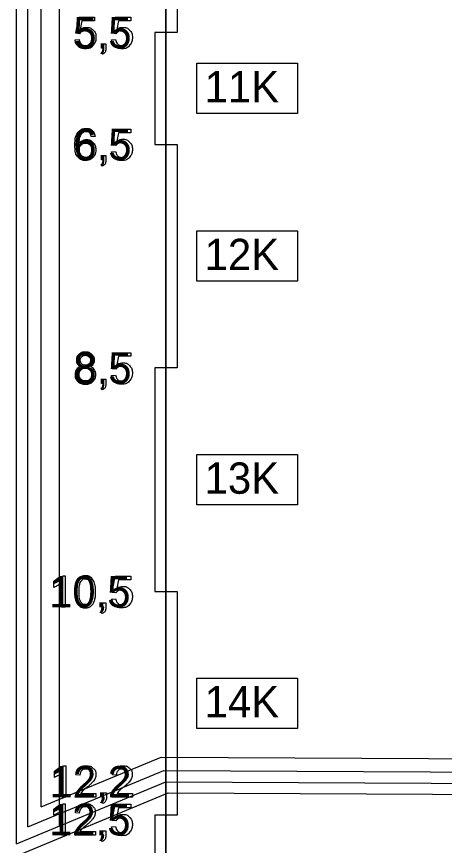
# Model space of a CAD drawing. Extents: x 532503 to 539665, y 6557663 to 6561526.
# Drawn here: x 538143.1 to 538219.7, y 6559684.2 to 6559832.5 of the extents above; entities that cross this region are included whole.
import ezdxf

# ---------------------------------------------------------------- set-up
doc = ezdxf.new("R2010")
doc.units = 0
for name, color, linetype in [('GEOLPUNKT', 7, 'Continuous'), ('illumineerimisjooned', 7, 'Continuous'), ('PIIR', 7, 'Continuous'), ('Plokid', 7, 'Continuous'), ('Proovid', 7, 'Continuous'), ('RELJEEF', 7, 'Continuous')]:
    doc.layers.add(name, color=color, linetype=linetype)

msp = doc.modelspace()

# ---------------------------------------------------------------- linework, layer by layer
at = {"layer": 'GEOLPUNKT'}
msp.add_line((538169.83, 6559939.6), (538169.83, 6559639.6), dxfattribs=at)
at = {"layer": 'illumineerimisjooned'}
msp.add_line((538145.11, 6559687.5), (538145.11, 6559941.71), dxfattribs=at)
msp.add_lwpolyline([(538145.11, 6559687.5), (538169.44, 6559697.61), (538288.54, 6559697), (538442.63, 6559688.61)], dxfattribs=at)
at = {"layer": 'PIIR'}
msp.add_line((538143.11, 6559684.5), (538143.11, 6559941.71), dxfattribs=at)
msp.add_lwpolyline([(538143.11, 6559684.5), (538169.83, 6559695.6), (538288.48, 6559695), (538467.68, 6559685.24), (538608.55, 6559672.2), (538715.29, 6559665.8)], dxfattribs=at)
at = {"layer": 'Plokid'}
msp.add_line((538147.51, 6559691.1), (538147.51, 6559935.16), dxfattribs=at)
for points in [[(538147.51, 6559691.1), (538168.96, 6559700.01), (538288.61, 6559699.4), (538440.23, 6559691.14)], [(538143.88, 6559682.66), (538170.22, 6559693.6), (538288.42, 6559693.01), (538467.54, 6559683.25), (538608.39, 6559670.21), (538713.29, 6559663.92)]]:
    msp.add_lwpolyline(points, dxfattribs=at)
at = {"layer": 'Proovid'}
for points in [[(538169.83, 6559869.6), (538171.83, 6559869.6), (538171.83, 6559829.6), (538169.83, 6559829.6)], [(538169.83, 6559829.6), (538167.83, 6559829.6), (538167.83, 6559809.6), (538169.83, 6559809.6)], [(538175.36, 6559824.1), (538193.36, 6559824.1), (538193.36, 6559815.1), (538175.36, 6559815.1)], [(538169.83, 6559809.6), (538171.83, 6559809.6), (538171.83, 6559769.6), (538169.83, 6559769.6)], [(538175.36, 6559794.1), (538193.36, 6559794.1), (538193.36, 6559785.1), (538175.36, 6559785.1)], [(538169.83, 6559769.6), (538167.83, 6559769.6), (538167.83, 6559729.6), (538169.83, 6559729.6)], [(538175.36, 6559754.1), (538193.36, 6559754.1), (538193.36, 6559745.1), (538175.36, 6559745.1)], [(538169.83, 6559729.6), (538171.83, 6559729.6), (538171.83, 6559689.6), (538169.83, 6559689.6)], [(538175.36, 6559714.1), (538193.36, 6559714.1), (538193.36, 6559705.1), (538175.36, 6559705.1)], [(538169.83, 6559689.6), (538167.83, 6559689.6), (538167.83, 6559639.6), (538169.83, 6559639.6)]]:
    msp.add_lwpolyline(points, close=True, dxfattribs=at)
for points in [[(538154.36, 6559829.37), (538153.72, 6559829.46), (538154.26, 6559832.33), (538157.04, 6559832.33), (538157.04, 6559831.68), (538154.81, 6559831.68), (538154.51, 6559830.17)], [(538160.88, 6559829.37), (538160.24, 6559829.46), (538160.78, 6559832.33), (538163.57, 6559832.33), (538163.57, 6559831.68), (538161.33, 6559831.68), (538161.03, 6559830.17)], [(538153.59, 6559828.27), (538154.32, 6559828.33)], [(538158.32, 6559826.8), (538158.32, 6559827.59), (538159.1, 6559827.59), (538159.1, 6559826.8)], [(538160.12, 6559828.27), (538160.84, 6559828.33)], [(538158.46, 6559825.7), (538158.27, 6559825.99)], [(538158.7, 6559826.8), (538158.32, 6559826.8)], [(538160.88, 6559809.37), (538160.24, 6559809.46), (538160.78, 6559812.33), (538163.57, 6559812.33), (538163.57, 6559811.68), (538161.33, 6559811.68), (538161.03, 6559810.17)], [(538157.17, 6559811.03), (538156.48, 6559810.98)], [(538160.12, 6559808.27), (538160.84, 6559808.33)], [(538158.32, 6559806.8), (538158.32, 6559807.59), (538159.1, 6559807.59), (538159.1, 6559806.8)], [(538158.7, 6559806.8), (538158.32, 6559806.8)], [(538158.46, 6559805.7), (538158.27, 6559805.99)], [(538160.88, 6559769.37), (538160.24, 6559769.46), (538160.78, 6559772.33), (538163.57, 6559772.33), (538163.57, 6559771.68), (538161.33, 6559771.68), (538161.03, 6559770.17)], [(538160.12, 6559768.27), (538160.84, 6559768.33)], [(538158.32, 6559766.8), (538158.32, 6559767.59), (538159.1, 6559767.59), (538159.1, 6559766.8)], [(538158.7, 6559766.8), (538158.32, 6559766.8)], [(538158.46, 6559765.7), (538158.27, 6559765.99)], [(538151.39, 6559732.43), (538151.83, 6559732.43), (538151.83, 6559726.8)], [(538160.88, 6559729.37), (538160.24, 6559729.46), (538160.78, 6559732.33), (538163.57, 6559732.33), (538163.57, 6559731.68), (538161.33, 6559731.68), (538161.03, 6559730.17)], [(538149.77, 6559730.36), (538149.77, 6559731.02)], [(538151.83, 6559726.8), (538151.14, 6559726.8), (538151.14, 6559731.19)], [(538160.12, 6559728.27), (538160.84, 6559728.33)], [(538158.32, 6559726.8), (538158.32, 6559727.59), (538159.1, 6559727.59), (538159.1, 6559726.8)], [(538158.7, 6559726.8), (538158.32, 6559726.8)], [(538158.46, 6559725.7), (538158.27, 6559725.99)], [(538151.49, 6559698.43), (538151.93, 6559698.43), (538151.93, 6559692.8)], [(538149.87, 6559696.36), (538149.87, 6559697.02)], [(538151.93, 6559692.8), (538151.25, 6559692.8), (538151.25, 6559697.19)], [(538154.44, 6559696.74), (538153.74, 6559696.81)], [(538160.97, 6559696.74), (538160.26, 6559696.81)], [(538158.42, 6559692.8), (538158.42, 6559693.59), (538159.2, 6559693.59), (538159.2, 6559692.8)], [(538157.31, 6559693.47), (538157.31, 6559692.8), (538153.61, 6559692.8)], [(538154.56, 6559693.47), (538157.31, 6559693.47)], [(538158.81, 6559692.8), (538158.42, 6559692.8)], [(538163.83, 6559693.47), (538163.83, 6559692.8), (538160.13, 6559692.8)], [(538161.09, 6559693.47), (538163.83, 6559693.47)], [(538151.39, 6559691.65), (538151.83, 6559691.65), (538151.83, 6559686.03)], [(538158.56, 6559691.7), (538158.37, 6559691.99)], [(538160.88, 6559688.6), (538160.24, 6559688.68), (538160.78, 6559691.56), (538163.57, 6559691.56), (538163.57, 6559690.9), (538161.33, 6559690.9), (538161.03, 6559689.4)], [(538149.77, 6559689.58), (538149.77, 6559690.25)], [(538151.83, 6559686.03), (538151.14, 6559686.03), (538151.14, 6559690.41)], [(538154.34, 6559689.96), (538153.63, 6559690.03)], [(538157.21, 6559686.69), (538157.21, 6559686.03), (538153.51, 6559686.03)], [(538154.46, 6559686.69), (538157.21, 6559686.69)], [(538158.32, 6559686.03), (538158.32, 6559686.81), (538159.1, 6559686.81), (538159.1, 6559686.03)], [(538160.12, 6559687.5), (538160.84, 6559687.56)], [(538158.46, 6559684.92), (538158.27, 6559685.21)], [(538158.7, 6559686.03), (538158.32, 6559686.03)]]:
    msp.add_lwpolyline(points, dxfattribs=at)
for points in [[(538154.51, 6559830.17), (538155.01, 6559830.52), (538155.57, 6559830.52), (538156.3, 6559830.52), (538156.8, 6559830.01), (538157.31, 6559829.51), (538157.31, 6559828.71), (538157.31, 6559827.95), (538156.86, 6559827.39), (538156.33, 6559826.71), (538155.39, 6559826.71), (538154.63, 6559826.71), (538154.15, 6559827.14), (538153.66, 6559827.57), (538153.59, 6559828.27)], [(538161.03, 6559830.17), (538161.53, 6559830.52), (538162.09, 6559830.52), (538162.82, 6559830.52), (538163.33, 6559830.01), (538163.83, 6559829.51), (538163.83, 6559828.71), (538163.83, 6559827.95), (538163.39, 6559827.39), (538162.85, 6559826.71), (538161.92, 6559826.71), (538161.15, 6559826.71), (538160.67, 6559827.14), (538160.19, 6559827.57), (538160.12, 6559828.27)], [(538154.32, 6559828.33), (538154.4, 6559827.81), (538154.69, 6559827.54), (538154.98, 6559827.27), (538155.39, 6559827.27), (538155.89, 6559827.27), (538156.24, 6559827.65), (538156.58, 6559828.02), (538156.58, 6559828.65), (538156.58, 6559829.23), (538156.25, 6559829.58), (538155.92, 6559829.92), (538155.38, 6559829.92), (538155.05, 6559829.92), (538154.78, 6559829.76), (538154.52, 6559829.61), (538154.36, 6559829.37)], [(538160.84, 6559828.33), (538160.92, 6559827.81), (538161.21, 6559827.54), (538161.5, 6559827.27), (538161.92, 6559827.27), (538162.42, 6559827.27), (538162.76, 6559827.65), (538163.1, 6559828.02), (538163.1, 6559828.65), (538163.1, 6559829.23), (538162.77, 6559829.58), (538162.44, 6559829.92), (538161.9, 6559829.92), (538161.57, 6559829.92), (538161.3, 6559829.76), (538161.04, 6559829.61), (538160.88, 6559829.37)], [(538158.27, 6559825.99), (538158.49, 6559826.09), (538158.59, 6559826.27), (538158.69, 6559826.46), (538158.7, 6559826.8)], [(538159.1, 6559826.8), (538159.1, 6559826.37), (538158.94, 6559826.11), (538158.79, 6559825.84), (538158.46, 6559825.7)], [(538156.48, 6559810.98), (538156.39, 6559811.38), (538156.22, 6559811.57), (538155.94, 6559811.86), (538155.53, 6559811.86), (538155.21, 6559811.86), (538154.95, 6559811.68), (538154.63, 6559811.44), (538154.44, 6559810.99), (538154.26, 6559810.53), (538154.25, 6559809.69), (538154.5, 6559810.07), (538154.86, 6559810.25), (538155.22, 6559810.44), (538155.61, 6559810.44), (538156.3, 6559810.44), (538156.78, 6559809.93), (538157.27, 6559809.43), (538157.27, 6559808.62), (538157.27, 6559808.1), (538157.04, 6559807.64), (538156.81, 6559807.19), (538156.41, 6559806.95), (538156.02, 6559806.71), (538155.51, 6559806.71), (538154.65, 6559806.71), (538154.11, 6559807.34), (538153.56, 6559807.97), (538153.56, 6559809.43), (538153.56, 6559811.05), (538154.17, 6559811.78), (538154.69, 6559812.43), (538155.58, 6559812.43), (538156.24, 6559812.43), (538156.66, 6559812.06), (538157.08, 6559811.68), (538157.17, 6559811.03)], [(538154.35, 6559808.62), (538154.35, 6559808.26), (538154.51, 6559807.94), (538154.66, 6559807.61), (538154.93, 6559807.44), (538155.2, 6559807.27), (538155.5, 6559807.27), (538155.93, 6559807.27), (538156.24, 6559807.63), (538156.56, 6559807.98), (538156.56, 6559808.58), (538156.56, 6559809.16), (538156.25, 6559809.5), (538155.94, 6559809.83), (538155.47, 6559809.83), (538155, 6559809.83), (538154.68, 6559809.5), (538154.35, 6559809.16), (538154.35, 6559808.62)], [(538161.03, 6559810.17), (538161.53, 6559810.52), (538162.09, 6559810.52), (538162.82, 6559810.52), (538163.33, 6559810.01), (538163.83, 6559809.51), (538163.83, 6559808.71), (538163.83, 6559807.95), (538163.39, 6559807.39), (538162.85, 6559806.71), (538161.92, 6559806.71), (538161.15, 6559806.71), (538160.67, 6559807.14), (538160.19, 6559807.57), (538160.12, 6559808.27)], [(538160.84, 6559808.33), (538160.92, 6559807.81), (538161.21, 6559807.54), (538161.5, 6559807.27), (538161.92, 6559807.27), (538162.42, 6559807.27), (538162.76, 6559807.65), (538163.1, 6559808.02), (538163.1, 6559808.65), (538163.1, 6559809.23), (538162.77, 6559809.58), (538162.44, 6559809.92), (538161.9, 6559809.92), (538161.57, 6559809.92), (538161.3, 6559809.76), (538161.04, 6559809.61), (538160.88, 6559809.37)], [(538158.27, 6559805.99), (538158.49, 6559806.09), (538158.59, 6559806.27), (538158.69, 6559806.46), (538158.7, 6559806.8)], [(538159.1, 6559806.8), (538159.1, 6559806.37), (538158.94, 6559806.11), (538158.79, 6559805.84), (538158.46, 6559805.7)], [(538154.66, 6559769.84), (538154.23, 6559770), (538154.02, 6559770.29), (538153.81, 6559770.58), (538153.81, 6559770.98), (538153.81, 6559771.59), (538154.25, 6559772.01), (538154.69, 6559772.43), (538155.42, 6559772.43), (538156.15, 6559772.43), (538156.6, 6559772), (538157.04, 6559771.58), (538157.04, 6559770.97), (538157.04, 6559770.58), (538156.84, 6559770.29), (538156.63, 6559770), (538156.22, 6559769.84), (538156.73, 6559769.68), (538157, 6559769.3), (538157.27, 6559768.93), (538157.27, 6559768.41), (538157.27, 6559767.69), (538156.77, 6559767.2), (538156.26, 6559766.71), (538155.43, 6559766.71), (538154.6, 6559766.71), (538154.09, 6559767.2), (538153.59, 6559767.69), (538153.59, 6559768.43), (538153.59, 6559768.97), (538153.86, 6559769.34), (538154.14, 6559769.71), (538154.66, 6559769.84)], [(538154.52, 6559771.01), (538154.52, 6559770.61), (538154.77, 6559770.36), (538155.03, 6559770.11), (538155.44, 6559770.11), (538155.83, 6559770.11), (538156.08, 6559770.36), (538156.33, 6559770.61), (538156.33, 6559770.97), (538156.33, 6559771.35), (538156.08, 6559771.61), (538155.82, 6559771.86), (538155.43, 6559771.86), (538155.03, 6559771.86), (538154.78, 6559771.61), (538154.52, 6559771.36), (538154.52, 6559771.01)], [(538154.29, 6559768.42), (538154.29, 6559768.13), (538154.43, 6559767.85), (538154.57, 6559767.58), (538154.85, 6559767.43), (538155.12, 6559767.27), (538155.44, 6559767.27), (538155.93, 6559767.27), (538156.25, 6559767.59), (538156.57, 6559767.91), (538156.57, 6559768.4), (538156.57, 6559768.9), (538156.24, 6559769.22), (538155.91, 6559769.55), (538155.41, 6559769.55), (538154.93, 6559769.55), (538154.61, 6559769.22), (538154.29, 6559768.9), (538154.29, 6559768.42)], [(538161.03, 6559770.17), (538161.53, 6559770.52), (538162.09, 6559770.52), (538162.82, 6559770.52), (538163.33, 6559770.01), (538163.83, 6559769.51), (538163.83, 6559768.71), (538163.83, 6559767.95), (538163.39, 6559767.39), (538162.85, 6559766.71), (538161.92, 6559766.71), (538161.15, 6559766.71), (538160.67, 6559767.14), (538160.19, 6559767.57), (538160.12, 6559768.27)], [(538160.84, 6559768.33), (538160.92, 6559767.81), (538161.21, 6559767.54), (538161.5, 6559767.27), (538161.92, 6559767.27), (538162.42, 6559767.27), (538162.76, 6559767.65), (538163.1, 6559768.02), (538163.1, 6559768.65), (538163.1, 6559769.23), (538162.77, 6559769.58), (538162.44, 6559769.92), (538161.9, 6559769.92), (538161.57, 6559769.92), (538161.3, 6559769.76), (538161.04, 6559769.61), (538160.88, 6559769.37)], [(538158.27, 6559765.99), (538158.49, 6559766.09), (538158.59, 6559766.27), (538158.69, 6559766.46), (538158.7, 6559766.8)], [(538159.1, 6559766.8), (538159.1, 6559766.37), (538158.94, 6559766.11), (538158.79, 6559765.84), (538158.46, 6559765.7)], [(538149.77, 6559731.02), (538150.35, 6559731.29), (538150.78, 6559731.68), (538151.21, 6559732.06), (538151.39, 6559732.43)], [(538153.59, 6559729.57), (538153.59, 6559730.56), (538153.8, 6559731.17), (538154, 6559731.77), (538154.41, 6559732.1), (538154.81, 6559732.43), (538155.42, 6559732.43), (538155.87, 6559732.43), (538156.21, 6559732.24), (538156.55, 6559732.06), (538156.77, 6559731.72), (538156.99, 6559731.38), (538157.12, 6559730.89), (538157.24, 6559730.4), (538157.24, 6559729.57), (538157.24, 6559728.58), (538157.04, 6559727.98), (538156.84, 6559727.37), (538156.44, 6559727.04), (538156.03, 6559726.71), (538155.42, 6559726.71), (538154.61, 6559726.71), (538154.15, 6559727.29), (538153.59, 6559727.99), (538153.59, 6559729.57)], [(538151.14, 6559731.19), (538150.9, 6559730.95), (538150.49, 6559730.71), (538150.09, 6559730.47), (538149.77, 6559730.36)], [(538154.3, 6559729.57), (538154.3, 6559728.19), (538154.63, 6559727.73), (538154.95, 6559727.27), (538155.42, 6559727.27), (538155.89, 6559727.27), (538156.21, 6559727.73), (538156.54, 6559728.19), (538156.54, 6559729.57), (538156.54, 6559730.95), (538156.21, 6559731.4), (538155.89, 6559731.86), (538155.41, 6559731.86), (538154.94, 6559731.86), (538154.66, 6559731.46), (538154.3, 6559730.95), (538154.3, 6559729.57)], [(538161.03, 6559730.17), (538161.53, 6559730.52), (538162.09, 6559730.52), (538162.82, 6559730.52), (538163.33, 6559730.01), (538163.83, 6559729.51), (538163.83, 6559728.71), (538163.83, 6559727.95), (538163.39, 6559727.39), (538162.85, 6559726.71), (538161.92, 6559726.71), (538161.15, 6559726.71), (538160.67, 6559727.14), (538160.19, 6559727.57), (538160.12, 6559728.27)], [(538160.84, 6559728.33), (538160.92, 6559727.81), (538161.21, 6559727.54), (538161.5, 6559727.27), (538161.92, 6559727.27), (538162.42, 6559727.27), (538162.76, 6559727.65), (538163.1, 6559728.02), (538163.1, 6559728.65), (538163.1, 6559729.23), (538162.77, 6559729.58), (538162.44, 6559729.92), (538161.9, 6559729.92), (538161.57, 6559729.92), (538161.3, 6559729.76), (538161.04, 6559729.61), (538160.88, 6559729.37)], [(538158.27, 6559725.99), (538158.49, 6559726.09), (538158.59, 6559726.27), (538158.69, 6559726.46), (538158.7, 6559726.8)], [(538159.1, 6559726.8), (538159.1, 6559726.37), (538158.94, 6559726.11), (538158.79, 6559725.84), (538158.46, 6559725.7)], [(538149.87, 6559697.02), (538150.45, 6559697.29), (538150.88, 6559697.68), (538151.31, 6559698.06), (538151.49, 6559698.43)], [(538153.74, 6559696.81), (538153.81, 6559697.6), (538154.28, 6559698.01), (538154.76, 6559698.43), (538155.55, 6559698.43), (538156.36, 6559698.43), (538156.83, 6559697.98), (538157.3, 6559697.53), (538157.3, 6559696.87), (538157.3, 6559696.54), (538157.16, 6559696.21), (538157.02, 6559695.89), (538156.71, 6559695.53), (538156.39, 6559695.17), (538155.65, 6559694.54), (538155.03, 6559694.02), (538154.85, 6559693.84), (538154.68, 6559693.65), (538154.56, 6559693.47)], [(538160.26, 6559696.81), (538160.33, 6559697.6), (538160.8, 6559698.01), (538161.28, 6559698.43), (538162.08, 6559698.43), (538162.88, 6559698.43), (538163.35, 6559697.98), (538163.82, 6559697.53), (538163.82, 6559696.87), (538163.82, 6559696.54), (538163.68, 6559696.21), (538163.55, 6559695.89), (538163.23, 6559695.53), (538162.91, 6559695.17), (538162.17, 6559694.54), (538161.55, 6559694.02), (538161.38, 6559693.84), (538161.2, 6559693.65), (538161.09, 6559693.47)], [(538151.25, 6559697.19), (538151, 6559696.95), (538150.6, 6559696.71), (538150.19, 6559696.47), (538149.87, 6559696.36)], [(538153.61, 6559692.8), (538153.6, 6559693.05), (538153.69, 6559693.28), (538153.83, 6559693.66), (538154.14, 6559694.03), (538154.45, 6559694.39), (538155.04, 6559694.87), (538155.95, 6559695.62), (538156.27, 6559696.06), (538156.59, 6559696.5), (538156.59, 6559696.89), (538156.59, 6559697.3), (538156.3, 6559697.58), (538156.01, 6559697.86), (538155.54, 6559697.86), (538155.04, 6559697.86), (538154.75, 6559697.56), (538154.45, 6559697.26), (538154.44, 6559696.74)], [(538160.13, 6559692.8), (538160.12, 6559693.05), (538160.21, 6559693.28), (538160.35, 6559693.66), (538160.66, 6559694.03), (538160.97, 6559694.39), (538161.56, 6559694.87), (538162.47, 6559695.62), (538162.79, 6559696.06), (538163.11, 6559696.5), (538163.11, 6559696.89), (538163.11, 6559697.3), (538162.82, 6559697.58), (538162.53, 6559697.86), (538162.06, 6559697.86), (538161.56, 6559697.86), (538161.27, 6559697.56), (538160.97, 6559697.26), (538160.97, 6559696.74)], [(538158.37, 6559691.99), (538158.59, 6559692.09), (538158.69, 6559692.27), (538158.79, 6559692.46), (538158.81, 6559692.8)], [(538159.2, 6559692.8), (538159.2, 6559692.37), (538159.05, 6559692.11), (538158.89, 6559691.84), (538158.56, 6559691.7)], [(538149.77, 6559690.25), (538150.35, 6559690.52), (538150.78, 6559690.9), (538151.21, 6559691.29), (538151.39, 6559691.65)], [(538153.51, 6559686.03), (538153.5, 6559686.28), (538153.59, 6559686.51), (538153.73, 6559686.89), (538154.04, 6559687.25), (538154.35, 6559687.62), (538154.94, 6559688.1), (538155.85, 6559688.85), (538156.17, 6559689.29), (538156.49, 6559689.72), (538156.49, 6559690.11), (538156.49, 6559690.52), (538156.2, 6559690.8), (538155.91, 6559691.08), (538155.44, 6559691.08), (538154.94, 6559691.08), (538154.64, 6559690.79), (538154.35, 6559690.49), (538154.34, 6559689.96)], [(538153.63, 6559690.03), (538153.71, 6559690.82), (538154.18, 6559691.24), (538154.65, 6559691.65), (538155.45, 6559691.65), (538156.26, 6559691.65), (538156.73, 6559691.2), (538157.2, 6559690.76), (538157.2, 6559690.1), (538157.2, 6559689.76), (538157.06, 6559689.44), (538156.92, 6559689.11), (538156.6, 6559688.75), (538156.29, 6559688.39), (538155.55, 6559687.77), (538154.93, 6559687.25), (538154.75, 6559687.06), (538154.58, 6559686.88), (538154.46, 6559686.69)], [(538151.14, 6559690.41), (538150.9, 6559690.17), (538150.49, 6559689.94), (538150.09, 6559689.7), (538149.77, 6559689.58)], [(538161.03, 6559689.4), (538161.53, 6559689.75), (538162.09, 6559689.75), (538162.82, 6559689.75), (538163.33, 6559689.24), (538163.83, 6559688.73), (538163.83, 6559687.93), (538163.83, 6559687.17), (538163.39, 6559686.62), (538162.85, 6559685.94), (538161.92, 6559685.94), (538161.15, 6559685.94), (538160.67, 6559686.36), (538160.19, 6559686.79), (538160.12, 6559687.5)], [(538160.84, 6559687.56), (538160.92, 6559687.03), (538161.21, 6559686.77), (538161.5, 6559686.5), (538161.92, 6559686.5), (538162.42, 6559686.5), (538162.76, 6559686.87), (538163.1, 6559687.25), (538163.1, 6559687.87), (538163.1, 6559688.46), (538162.77, 6559688.8), (538162.44, 6559689.14), (538161.9, 6559689.14), (538161.57, 6559689.14), (538161.3, 6559688.99), (538161.04, 6559688.84), (538160.88, 6559688.6)], [(538158.27, 6559685.21), (538158.49, 6559685.31), (538158.59, 6559685.5), (538158.69, 6559685.68), (538158.7, 6559686.03)], [(538159.1, 6559686.03), (538159.1, 6559685.6), (538158.94, 6559685.33), (538158.79, 6559685.07), (538158.46, 6559684.92)]]:
    msp.add_open_spline(points, degree=3, dxfattribs=at)
at = {"layer": 'RELJEEF'}
msp.add_line((538150.73, 6559921.9), (538150.73, 6559687.67), dxfattribs=at)

# ---------------------------------------------------------------- texts
at = {"layer": 'Proovid'}
for s, p in [('5,5', (538153.27, 6559826.8)), ('11K', (538176.76, 6559817.1)), ('6,5', (538153.27, 6559806.8)), ('12K', (538176.76, 6559787.1)), ('8,5', (538153.27, 6559766.8)), ('13K', (538176.76, 6559747.1)), ('10,5', (538148.92, 6559726.8)), ('14K', (538176.76, 6559707.1)), ('12,2', (538149.02, 6559692.8)), ('12,5', (538148.92, 6559686.03))]:
    msp.add_text(s, height=5.6, dxfattribs=at).set_placement(p)

doc.saveas('drawing.dxf')
